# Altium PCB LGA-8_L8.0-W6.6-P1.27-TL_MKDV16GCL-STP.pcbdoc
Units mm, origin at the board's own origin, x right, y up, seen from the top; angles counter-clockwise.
Board outline 22.07 x 19.45 mm, 2 copper layers (Top Layer, Bottom Layer), stack 0 mm thick; 1 components, 0 nets, 8 pads, 0 vias.
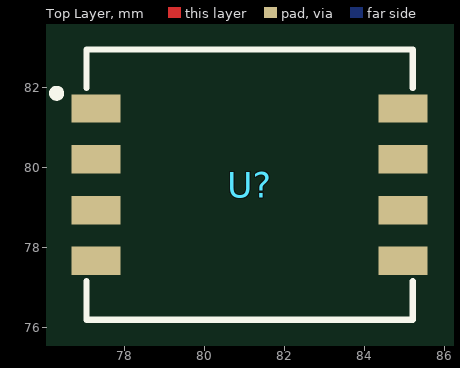
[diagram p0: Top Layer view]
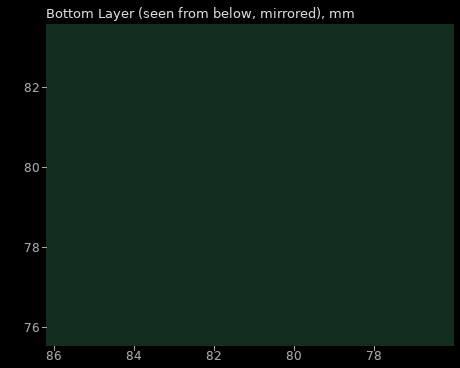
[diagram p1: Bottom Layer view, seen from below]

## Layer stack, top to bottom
Top Layer: signal copper (thickness not stored)
Bottom Layer: signal copper (thickness not stored)

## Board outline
91.92,69.85 69.85,69.85 69.85,89.302 91.92,89.302

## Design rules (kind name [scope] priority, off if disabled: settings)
PasteMaskExpansion "Paste Mask Expansion" [All] p1: expansion=0
SolderMaskExpansion "Solder Mask Expansion" [IsVia] p1: expansion=-25.4 istentingtop=TRUE
SolderMaskExpansion "Solder Mask Expansion" [All] p2: expansion=0.051 istentingtop=FALSE

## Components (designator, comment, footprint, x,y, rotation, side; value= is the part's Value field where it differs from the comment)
U? "" LGA-8_L8.0-W6.6-P1.27-TL_MKDV16GCL-STP 81.12,79.576 r0 top

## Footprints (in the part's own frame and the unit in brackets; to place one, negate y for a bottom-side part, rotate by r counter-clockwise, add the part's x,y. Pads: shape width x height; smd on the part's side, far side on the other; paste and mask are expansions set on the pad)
LGA-8_L8.0-W6.6-P1.27-TL_MKDV16GCL-STP [mm]
  rect 1.225x0.711 smd: 1(-3.837,1.905) 2(-3.837,0.635) 3(-3.837,-0.635) 4(-3.837,-1.905) 5(3.837,-1.905) 6(3.837,-0.635) 7(3.837,0.635) 8(3.837,1.905)
  silkscreen extent -4.92,-3.38 4.08,3.38

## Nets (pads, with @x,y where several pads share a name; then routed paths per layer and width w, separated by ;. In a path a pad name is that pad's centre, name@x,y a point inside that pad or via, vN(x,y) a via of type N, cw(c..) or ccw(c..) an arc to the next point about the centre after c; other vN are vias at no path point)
pads on no net: U?.1 U?.2 U?.3 U?.4 U?.5 U?.6 U?.7 U?.8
